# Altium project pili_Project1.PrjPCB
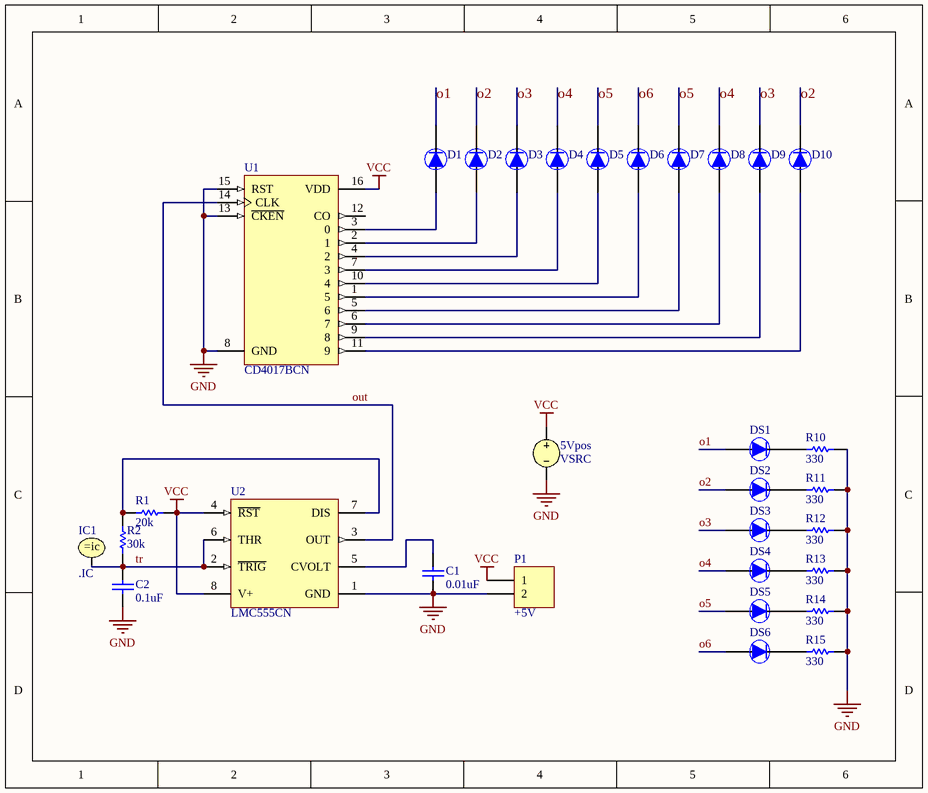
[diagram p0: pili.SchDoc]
1 sheet, 31 parts. Net scope: global (net labels, ports and power ports of the same name join across sheets).
Board files: pili.PcbDoc, pili2.PcbDoc

## Sheet pili.SchDoc
size 172 x 147 mm

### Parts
5Vpos  VSRC
C1  value 0.01uF  [C200 - 1]  (hidden comment: Cap)
C2  value 0.1uF  [C200 - 1]  (hidden comment: Cap)
D1  1N914  [D400]  (value not drawn)
D2  1N914  [D400]  (value not drawn)
D3  1N914  [D400]  (value not drawn)
D4  1N914  [D400]  (value not drawn)
D5  1N914  [D400]  (value not drawn)
D6  1N914  [D400]  (value not drawn)
D7  1N914  [D400]  (value not drawn)
D8  1N914  [D400]  (value not drawn)
D9  1N914  [D400]  (value not drawn)
D10  1N914  [D400]  (value not drawn)
DS1  1N914  [D400-1]  (value not drawn)
DS2  1N914  [D400-1]  (value not drawn)
DS3  1N914  [D400-1]  (value not drawn)
DS4  1N914  [D400-1]  (value not drawn)
DS5  1N914  [D400-1]  (value not drawn)
DS6  1N914  [D400-1]  (value not drawn)
IC1  .IC
P1  +5V  [HEADER 2 PW-0.2]
R1  value 20k  [AXIAL-0.3]  (hidden comment: 1k)
R2  value 30k  [AXIAL-0.3]  (hidden comment: 1k)
R10  value 330  [AXIAL-0.3]  (hidden comment: 1k)
R11  value 330  [AXIAL-0.3]  (hidden comment: 1k)
R12  value 330  [AXIAL-0.3]  (hidden comment: 1k)
R13  value 330  [AXIAL-0.3]  (hidden comment: 1k)
R14  value 330  [AXIAL-0.3]  (hidden comment: 1k)
R15  value 330  [AXIAL-0.3]  (hidden comment: 1k)
U1  CD4017BCN  [DIP16_4017]
U2  LMC555CN  [N08E_555]

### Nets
GND: 5Vpos.2 C1.2 C2.2 P1.2 R10.1 R11.1 R12.1 R13.1 R14.1 R15.1 U1.8(GND) U1.13(~{CKEN}) U1.15(RST) U2.1(GND)
VCC: 5Vpos.1 P1.1 R1.2 U1.16(VDD) U2.4(~{RST}) U2.8(V+)
o1: D1.2(K) DS1.1(A)
o2: D2.2(K) D10.2(K) DS2.1(A)
o3: D3.2(K) D9.2(K) DS3.1(A)
o4: D4.2(K) D8.2(K) DS4.1(A)
o5: D5.2(K) D7.2(K) DS5.1(A)
o6: D6.2(K) DS6.1(A)
out: U1.14(CLK) U2.3(OUT)
tr: C2.1 IC1.1 R2.1 U2.2(~{TRIG}) U2.6(THR)
NetC1_1: C1.1 U2.5(CVOLT)
NetD1_1: D1.1(A) U1.3(0)
NetD2_1: D2.1(A) U1.2(1)
NetD3_1: D3.1(A) U1.4(2)
NetD4_1: D4.1(A) U1.7(3)
NetD5_1: D5.1(A) U1.10(4)
NetD6_1: D6.1(A) U1.1(5)
NetD7_1: D7.1(A) U1.5(6)
NetD8_1: D8.1(A) U1.6(7)
NetD9_1: D9.1(A) U1.9(8)
NetD10_1: D10.1(A) U1.11(9)
NetDS1_2: DS1.2(K) R10.2
NetDS2_2: DS2.2(K) R11.2
NetDS3_2: DS3.2(K) R12.2
NetDS4_2: DS4.2(K) R13.2
NetDS5_2: DS5.2(K) R14.2
NetDS6_2: DS6.2(K) R15.2
NetR1_1: R1.1 R2.2 U2.7(DIS)

Not connected (* = marked no-connect by the designer): U1 12(CO)

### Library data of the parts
5Vpos = VSRC: Voltage Source; Note: PCB Footprint - Not required; Value: +5
C1 C2 = Cap: Capacitor
D1-D10 DS1-DS6 = 1N914: High Conductance Fast Diode
IC1 = .IC: Initial Condition
P1 = Header 2: Header, 2-Pin
R1 R2 R10-R15 = Res: Resistor
U1 = CD4017BCN: Decade Counter/Divider with 10 Decoded Outputs
U2 = LMC555CN: CMOS Timer; Manufacturer: National Semiconductor; CompType: Analog IC; PackageTopMarking: NSUZXYTT*LMC*555CN; PowerWise: N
